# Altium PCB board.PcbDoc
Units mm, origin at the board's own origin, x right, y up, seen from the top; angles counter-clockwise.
Board outline 68 x 91 mm, 2 copper layers (Top Layer, Bottom Layer), stack 0.396 mm thick; 85 components, 65 nets, 273 pads, 165 vias.
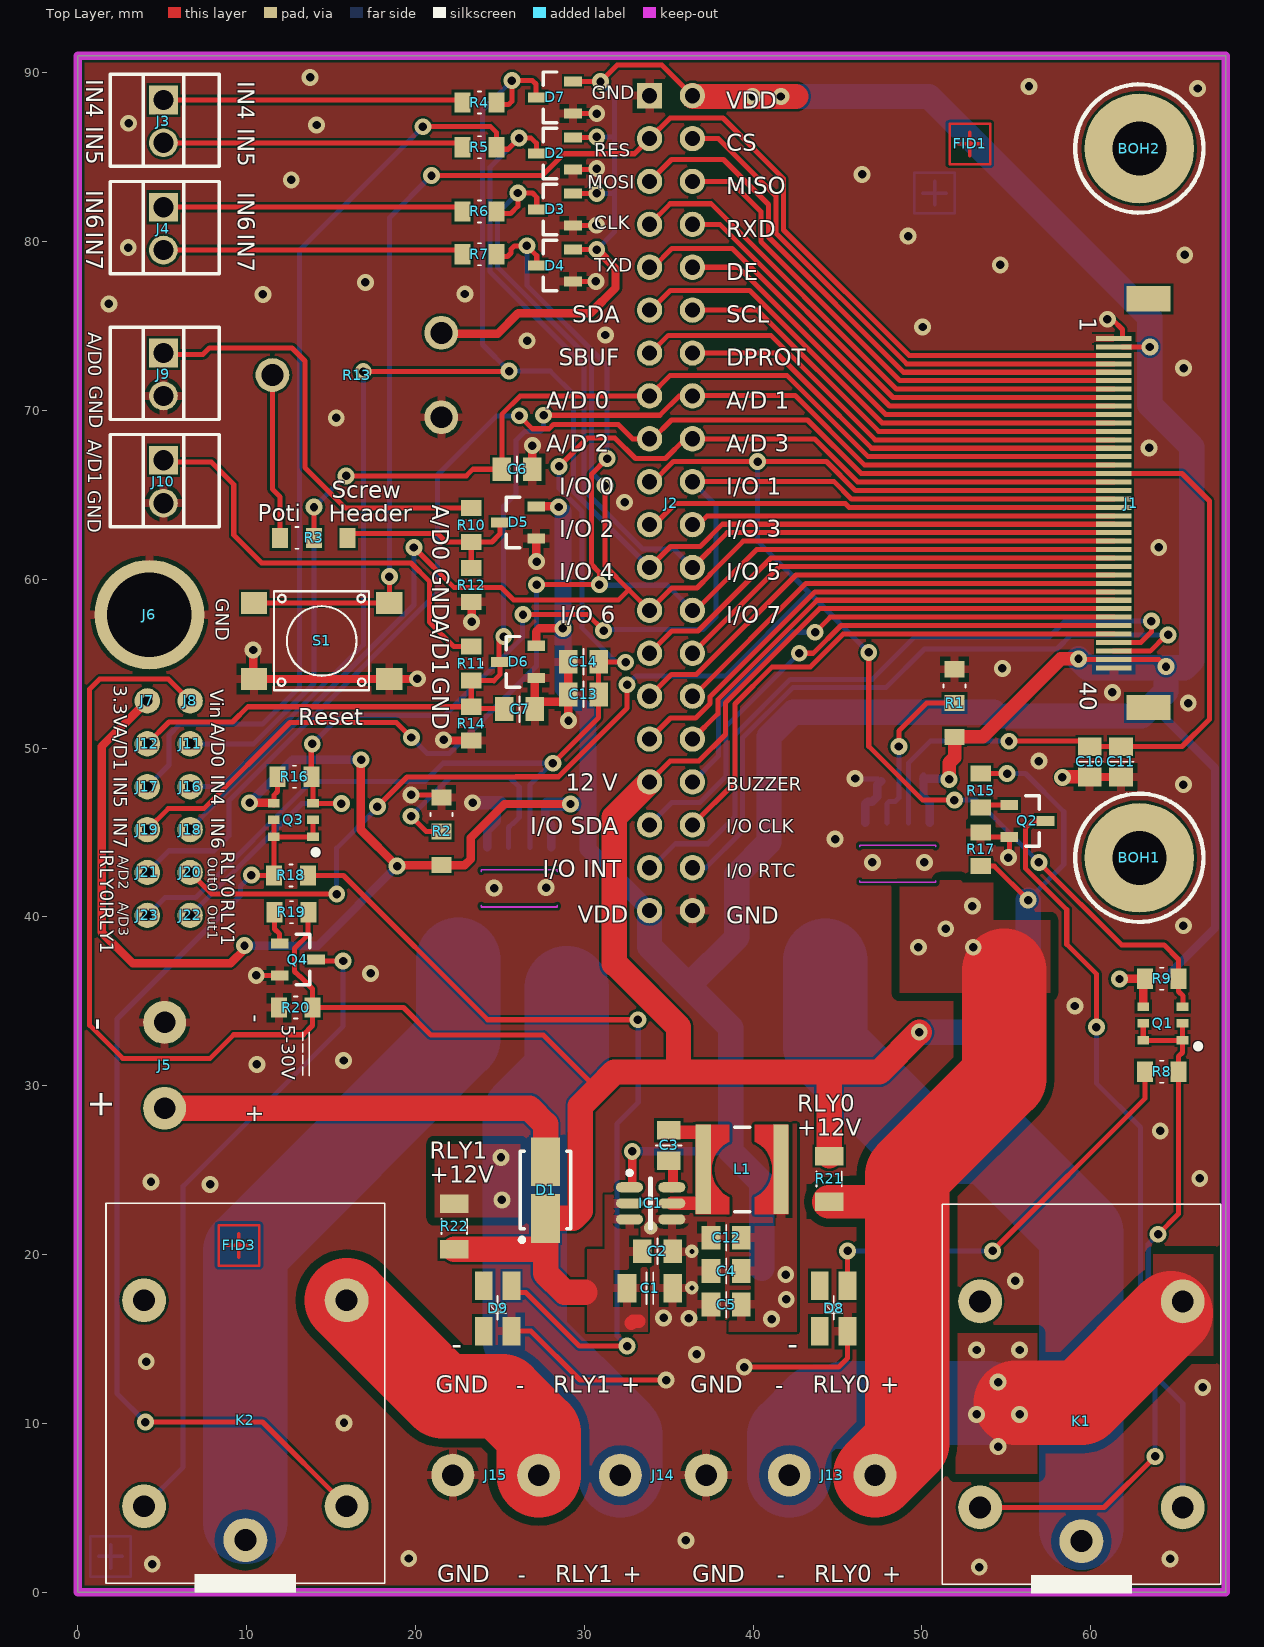
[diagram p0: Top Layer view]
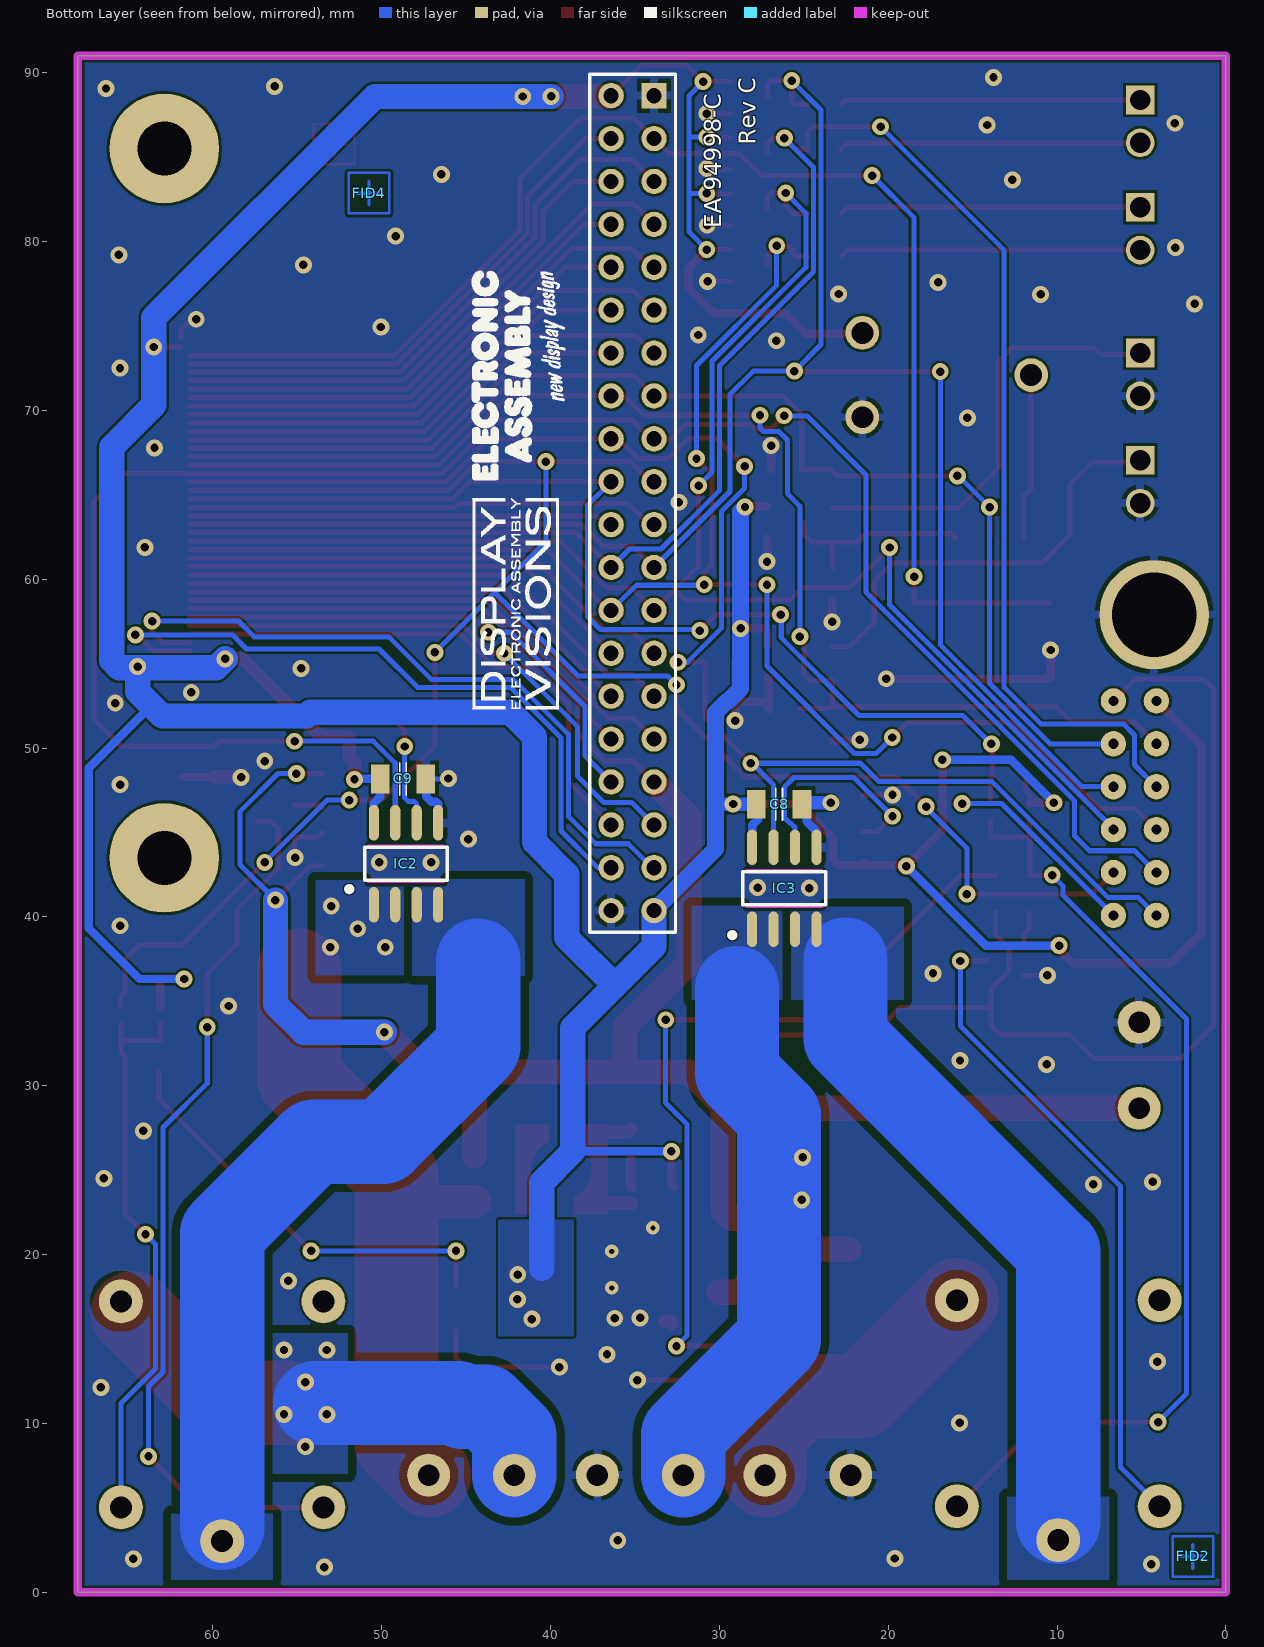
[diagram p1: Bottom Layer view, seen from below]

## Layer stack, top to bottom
Top Layer: signal copper 0.018
Dielectric: prepreg 0.36, FR-4, Dk 4.8
Bottom Layer: signal copper 0.018

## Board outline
0,0 68,0 68,91 0,91

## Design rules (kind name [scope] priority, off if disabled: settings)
Clearance Clearance_RelaisA [OnLayer('Keep-Out Layer') or InNet('K1IN') OR InNet('K1INAMP') OR InNet('K1OUT') OR InNet('K2IN') OR InNet('K2INAMP') OR InNet('K2OUT') vs InComponent('IC2') or InComponent('IC3')] p1: gap=0.2
Clearance Clearance_Relais [(InNet('K1IN') OR InNet('K1INAMP') OR InNet('K1OUT') OR InNet('K2IN') OR InNet('K2INAMP') OR InNet('K2OUT'))] p2: gap=0.5
Clearance Clearance-xPP-xTP-xTT [All] p3: gap=0.15
ComponentClearance [All] p1: gap=0.25 collisioncheckmode=3 verticalgap=0.25 showdistances=FALSE
DiffPairsRouting [All] p1: maxlimit=0.25 minlimit=0.25 mostfreqgap=0.25 maxuncoupledlength=12.5
Height [All] p1: minheight=0 maxheight=25 prefheight=12.5
HoleSize HoleSize-PTH [All] p1: absolutevalues=TRUE maxlimit=5 minlimit=0.25 maxpercent=80.000 minpercent=20.000
HoleToHoleClearance [All] p1: gap=0.15 allowstackedmicrovias=TRUE
MinimumAnnularRing MinimumAnnularRing_oval [InNetClass('Flash')] p1: minimumring=0
MinimumAnnularRing "Minimum IAR  >0.45mm" [((ObjectKind = 'Pad') OR (ObjectKind = 'Via')) And (Layer = 'MultiLayer') And (HoleDiameter > AsMM(0.45))] p2: minimumring=0.1 // minimum inner annular ring for pads > 0.45mm finished hole size
MinimumAnnularRing "Minimum IAR <=0.45mm" [((ObjectKind = 'Pad') OR (ObjectKind = 'Via')) And (Layer = 'MultiLayer') And (HoleDiameter <= AsMM(0.45))] p3: minimumring=0.25 // minimum inner annular ring for pads <= 0.45mm finished hole size
MinimumSolderMaskSliver [All] p1: minsoldermaskwidth=0.075
PlaneClearance PlaneClearance-IPI [All] p1: clearance=0.4
PlaneConnect [All] p1: planeconnectstyle=Relief reliefexpansion=0.4 reliefentries=4 reliefconductorwidth=0.4 reliefairgap=0.2
PolygonConnect PolygonConnectVia [All vs IsVia] p1: connectstyle=Direct reliefconductorwidth=0.254 reliefentries=4 polygonreliefangle="90 Angle" airgapwidth=0.254
PolygonConnect PolygonConnectRelais [InNet('K1IN') or InNet('K1INAMP') or InNet('K2IN') or InNet('K2INAMP') or InNet('K1OUT')] p2: connectstyle=Direct reliefconductorwidth=0.254 reliefentries=4 polygonreliefangle="90 Angle" airgapwidth=0.254
PolygonConnect PolygonConnect-xTW [All] p3: connectstyle=Relief reliefconductorwidth=0.5 reliefentries=4 polygonreliefangle="90 Angle" airgapwidth=0.254
RoutingCorners [All] p1: cornerstyle=45-Degree minsetback=2.5 maxsetback=2.5
RoutingVias "RoutingVias > 0.45mm" [(ObjectKind = 'Via') And (HoleDiameter > AsMM(0.45))] p1: holewidth=0.5 width=1 viastyle="Through Hole" minholewidth=0.45 minwidth=0.95 maxholewidth=0.9 maxwidth=1.4 // finishet hole size > 0.45mm
RoutingVias "RoutingVias <= 0.45mm" [(ObjectKind = 'Via') And (HoleDiameter <= AsMM(0.45))] p2: holewidth=0.3 width=0.8 viastyle="Through Hole" minholewidth=0.25 minwidth=0.7 maxholewidth=0.5 maxwidth=1 // finishet hole size <= 0.45mm
SilkToSilkClearance [All] p1: silktosilkclearance=0.05
SilkscreenOverComponentPads [All] p1: minsilkscreentomaskgap=0.1
SolderMaskExpansion SolderMaskExpansionVia [IsVia] p1: expansion=-2
SolderMaskExpansion [All] p2: expansion=0.1
Width Relais [(InNet('K1IN') OR InNet('K1INAMP') OR InNet('K1OUT') OR InNet('K2IN') OR InNet('K2INAMP') OR InNet('K2OUT'))] p1: maxlimit=10 minlimit=2 preferedwidth=5
Width Width-xTW [All] p2: maxlimit=1.5 minlimit=0.15 preferedwidth=0.3
17 further rules are at their usual default settings.

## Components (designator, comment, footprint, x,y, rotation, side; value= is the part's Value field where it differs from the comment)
BOH1 "Bohrung" BOH_3_2 62.868,43.5 r0 top locked
BOH2 "Bohrung" BOH_3_2 62.868,85.5 r0 top locked
C1 "C1206" C1206 33.884,18.009 r180 top
C2 "C0805" C0805 34.334,20.193 r180 top
C3 "C0805" C0805 35.001,26.467 r270 top
C4 "C0805" C0805 38.405,19.03 r0 top
C5 "C0805" C0805 38.404,17.044 r0 top
C6 "C0805" C0805 26.019,66.506 r180 top
C7 "C0805" C0805 26.171,52.308 r180 top
C8 "C1206" C1206 26.458,46.669 r180 bottom
C9 "C1206" C1206 48.734,48.167 r180 bottom
C10 "C0805" C0805 59.928,49.183 r90 top
C11 "C0805" C0805 61.782,49.183 r90 top
C12 "C0805" C0805 38.405,21.006 r0 top
C13 "C0805" C0805 29.956,53.171 r0 top
C14 "C0805" C0805 29.956,55.102 r0 top
D1 "B330A" SMA 27.711,23.825 r90 top
D2 "BAT54S" SOT23-3 28.262,85.209 r180 top
D3 "BAT54S" SOT23-3 28.262,81.89 r180 top
D4 "BAT54S" SOT23-3 28.262,78.571 r180 top
D5 "BAT54S" SOT23-3 26.078,63.357 r180 top
D6 "BAT54S" SOT23-3 26.078,55.102 r180 top
D7 "BAT54S" SOT23-3 28.262,88.528 r180 top
D8 "LED_RedGreen" LEDDUO1210 44.767,16.815 r90 top
D9 "LED_RedGreen" LEDDUO1210 24.867,16.815 r90 top
FID1 "Fiducial" Fiducial 52.832,85.776 r90 top
FID2 "Fiducial" Fiducial 1.956,2.134 r90 bottom
FID3 "Fiducial" Fiducial 9.55,20.549 r90 top
FID4 "Fiducial" Fiducial 50.749,82.855 r90 bottom
IC1 "AP63203" TSOT26 33.934,23.038 r0 top
IC2 "CurrentMonitor" SOIC8_CURRENT 48.556,43.147 r90 bottom
IC3 "CurrentMonitor" SOIC8_CURRENT 26.153,41.69 r90 bottom
J1 "ZIFF40-0.5" "ZIFF40-0.5 - LONG" 61.868,74.25 r270 top locked
J2 "PINHeader2x20" PINHDR2X20 33.868,88.63 r0 top locked
J3 "SCREWHeader1x2" SCREWHDR1X2 5.082,85.836 r270 top
J4 "SCREWHeader1x2" SCREWHDR1X2 5.082,79.486 r270 top
J5 "AKS-2" SCREWHDR1X2_Big 5.147,33.749 r270 top
J6 "TP" PAD50/65 4.251,57.894 r270 top
J7 "TP" PAD06/15 4.124,52.789 r270 top
J8 "TP" PAD06/15 6.664,52.789 r270 top
J9 "AKM-2" SCREWHDR1X2 5.082,70.85 r270 top
J10 "SCREWHeader1x2" SCREWHDR1X2 5.082,64.5 r270 top
J11 "TP" PAD06/15 6.664,50.249 r270 top
J12 "TP" PAD06/15 4.124,50.249 r0 top
J13 "AKS-2" SCREWHDR1X2_Big 47.218,6.944 r180 top
J14 "AKS-2" SCREWHDR1X2_Big 37.218,6.944 r180 top
J15 "AKS-2" SCREWHDR1X2_Big 27.298,6.944 r180 top
J16 "TP" PAD06/15 6.664,47.709 r0 top
J17 "TP" PAD06/15 4.124,47.709 r0 top
J18 "TP" PAD06/15 6.664,45.169 r0 top
J19 "TP" PAD06/15 4.124,45.169 r270 top
J20 "TP" PAD06/15 6.664,42.629 r0 top
J21 "TP" PAD06/15 4.124,42.629 r270 top
J22 "TP" PAD06/15 6.664,40.089 r0 top
J23 "TP" PAD06/15 4.124,40.089 r0 top
K1 "G5LE" G5LE 59.442,3.029 r90 top
K2 "G5LE" G5LE 9.931,3.099 r90 top
L1 "Inductor-1919" L_1919 39.345,25.044 r90 top
Q1 "MFPS6702" TSOP-6 65.428,32.688 r180 top
Q2 "TRS847-C" SOT23-3 56.245,45.678 r0 top
Q3 "MFPS6702" TSOP-6 13.942,44.738 r180 top
Q4 "TRS847-C" SOT23-3 13.039,37.474 r0 top
R1 "R0805_double" R0805_double 51.927,53.663 r270 top
R2 "R0805_double" R0805_double 21.548,46.069 r270 top
R3 "R0805_double" R0805_double 12.988,62.442 r0 top
R4 "R0805" R0805 23.792,88.223 r0 top
R5 "R0805" R0805 23.792,85.582 r0 top
R6 "R0805" R0805 23.792,81.772 r0 top
R7 "R0805" R0805 23.792,79.232 r0 top
R8 "R0805" R0805 64.195,30.836 r0 top
R9 "R0805" R0805 64.195,36.331 r0 top
R10 "R0805" R0805 23.309,63.204 r90 top
R11 "R0805" R0805 23.309,55 r90 top
R12 "R0805" R0805 23.309,59.648 r90 top
R13 "V10" V10 16.535,72.085 r180 top
R14 "R0805" R0805 23.309,51.444 r90 top
R15 "R0805" R0805 53.476,47.482 r90 top
R16 "R0805" R0805 12.836,48.294 r180 top
R17 "R0805" R0805 53.476,44.002 r90 top
R18 "R0805" R0805 12.633,42.452 r180 top
R19 "R0805" R0805 12.66,40.268 r0 top
R20 "R0805" R0805 12.914,34.629 r180 top
R21 "R1206" R1206 44.501,24.486 r270 top
R22 "R1206" R1206 22.301,21.666 r90 top
S1 "SMD Taster" TASTER_SMD 14.453,56.337 r0 top

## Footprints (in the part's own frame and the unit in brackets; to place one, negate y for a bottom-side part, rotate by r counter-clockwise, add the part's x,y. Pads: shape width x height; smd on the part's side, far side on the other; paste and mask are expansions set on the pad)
BOH_3_2 [mm] "Bohrung 6.5 / 3.2 mm"
  round 6.5 hole 3.2: 1(0,0)
  silkscreen extent -3.8,-3.8 3.8,3.8
C0805 [mm] "Chip Capacitor, 2-Leads, Body 2,0x1,3mm, IPC Medium Density"
  rect 1.1x1.4 smd: 1(-0.9,0) 2(0.9,0)
  silkscreen extent 0,-0.76 0,0.76, body extent -1,-0.62 1,0.63, height 0.78
C1206 [mm] "Chip Capacitor, 2-Leads, Body 2 IPC Medium Density"
  rect 1.1x1.7 smd: 1(-1.35,0) 2(1.35,0)
  silkscreen extent -0.2,-0.95 0.2,0.95, body extent -1.6,-0.8 1.6,0.8, height 1
Fiducial [mm]
  Top Layer lines w0.15: -1.2,1.2 -1.2,-1.2 1.2,-1.2 1.2,1.2 -1.2,1.2
  Top Layer lines w0.2: 0,0.7 0,-0.7 ; -0.7,0 0.7,0
G5LE [mm] "Relais"
  round 2.6 hole 1.3: 1(0,0) 2(2,-6) 3(14.2,-6) 4(14.2,6) 5(2,6)
  silkscreen extent -3.1,-8.25 19.95,8.25, body extent -2.55,-8.25 19.95,8.25, height 19
L_1919 [mm] "WE-TPC_4828 Power Inductor, SMD, 2-Leads, body 4.8x4.8mm"
  rect 5.3x0.9 smd paste-403.566 mask-403.566: 1(0,2.3) 2(0,-2.3)
  Top Layer region: -2.65,0.75 -1.636,0.75 -1.636,0.75 -1.138,1.394 -0.407,1.753 0.407,1.753 1.138,1.394 1.636,0.75 1.636,0.75 2.65,0.75 2.65,0.75 2.65,2.75 -2.65,2.75
  Top Layer region: 2.65,-0.75 1.636,-0.75 1.636,-0.75 1.138,-1.394 0.407,-1.753 -0.407,-1.753 -1.138,-1.394 -1.636,-0.75 -1.636,-0.75 -2.65,-0.75 -2.65,-0.75 -2.65,-2.75 2.65,-2.75
  silkscreen extent -2.5,-0.45 2.5,0.45, body extent -2.4,-2.4 2.4,2.4, height 2.8
LEDDUO1210 [mm] "Duo Led 1210"
  rect 1.7x1.05 smd: 1(-1.35,0.825) 2(1.35,0.825) 3(-1.35,-0.825) 4(1.35,-0.825)
  silkscreen extent -0.66,-0.51 0.74,0.51, body extent -1.5,-1.25 1.5,1.25, height 1.35
PAD06/15 [mm]
  round 1.5 hole 0.6: 1(0,0)
PAD50/65 [mm] "Oszi_Klammer passt"
  round 6.5 hole 5: 1(0,0)
PINHDR2X20 [mm] "Stiftleiste"
  rect 1.5x1.5 hole 0.9: 1(0,0)
  round 1.5 hole 0.9: 2(2.54,0) 3(0,-2.54) 4(2.54,-2.54) 5(0,-5.08) 6(2.54,-5.08) 7(0,-7.62) 8(2.54,-7.62) 9(0,-10.16) 10(2.54,-10.16) 11(0,-12.7) 12(2.54,-12.7) 13(0,-15.24) 14(2.54,-15.24) 15(0,-17.78) 16(2.54,-17.78) 17(0,-20.32) 18(2.54,-20.32) 19(0,-22.86) 20(2.54,-22.86) 21(0,-25.4) 22(2.54,-25.4) 23(0,-27.94) 24(2.54,-27.94) 25(0,-30.48) 26(2.54,-30.48) 27(0,-33.02) 28(2.54,-33.02) 29(0,-35.56) 30(2.54,-35.56) 31(0,-38.1) 32(2.54,-38.1) 33(0,-40.64) 34(2.54,-40.64) 35(0,-43.18) 36(2.54,-43.18) 37(0,-45.72) 38(2.54,-45.72) 39(0,-48.26) 40(2.54,-48.26)
  body extent -1.27,-49.53 3.81,1.27, height 8.52
R0805 [mm] "Chip Resistor, 2-Leads, Body 2,0x1,3mm, IPC Medium Density"
  rect 0.95x1.2 smd: 1(-1,0) 2(1,0)
  silkscreen extent -0.1,-0.65 0.1,0.65, body extent -1,-0.62 1,0.63, height 0.78
R0805_double [mm] "Chip Resistor, 3-Leads, Body 4,0x1,3mm, IPC Medium Density"
  rect 0.95x1.2 smd: 1(-1,0) 2(1,0)
  rect 0.95x1.2 smd paste-10: 3(3,0)
  silkscreen extent -0.1,-0.65 0.1,0.65, body extent -1,-0.62 1,0.63, height 0.78
R1206 [mm] "Chip Resistor, 2-Leads, Body 3,1x1,6mm, IPC Medium Density"
  rect 1.1x1.7 smd: 1(-1.35,0) 2(1.35,0)
  silkscreen extent -0.45,-0.75 0.45,0.75, body extent -1.6,-0.8 1.6,0.8, height 1
SCREWHDR1X2 [mm] "Klemmleiste"
  rect 1.7x1.7 hole 1.2: 1(-2.54,0)
  round 1.7 hole 1.2: 2(0,0)
  silkscreen extent -4.06,-3.15 1.4,3.3, body extent -4.01,-3.25 1.47,3.25, height 8.55
SCREWHDR1X2_Big [mm] "AKM-2"
  round 2.54 hole 1.27: 1(0,0) 2(5.08,0)
  Mechanical 13 keep-out lines w0.102: -2.54,-3.81 7.468,-3.81 7.468,4.191
  body extent -3.1,-4 8.1,5, height 12.5
SMA [mm] "Molded Diode, 2-Leads, Body 4.3x2.6mm, IPC Low Density"
  rect 2.9x1.7 smd: 1(1.675,0) 2(-1.675,0)
  silkscreen extent -3.07,-1.5 2.3,1.52, body extent -2.3,-1.46 2.3,1.46, height 2.4
SOIC8_CURRENT [mm] "SOIC, 8-Leads, Body 4,9x3,9mm (max), Pitch 1,27mm, KeepOut"
  oval 2.1x0.6 smd: 1(-2.425,1.905) 2(-2.425,0.635) 3(-2.425,-0.635) 4(-2.425,-1.905) 5(2.425,-1.905) 6(2.425,-0.635) 7(2.425,0.635) 8(2.425,1.905)
  Keep-Out Layer lines w0.1: -1,-2.25 -1.1,-2.25 -1.1,2.25 -1,2.25 ; 1,-2.25 1.1,-2.25 1.1,2.25 1,2.25
  silkscreen extent -0.97,-2.45 0.98,2.45, body extent -3.1,-2.5 3.1,2.5, height 1.75
SOT23-3 [mm] "SOT23, 3-Leads, Body 3,0x2,5mm (max), Pitch 0,95mm, IPC Medium Density"
  rect 1.05x0.6 smd: 1(-1.075,0.95) 2(-1.075,-0.95) 3(1.075,0)
  silkscreen extent -0.1,-1.5 0.7,1.5, body extent -0.7,-1.5 0.7,1.5, height 1.1
TASTER_SMD [mm] "TASTS-1P7MM"
  rect 1.55x1.3 smd: 1(-4,2.25) 1(4,2.25) 2(-4,-2.25) 2(4,-2.25)
  silkscreen extent -2.82,-2.92 2.79,2.95, body extent -3.1,-3.1 3.1,3.1, height 6.9
TSOP-6 [mm]
  rect 0.7x0.5 smd: 1(0,0) 1(0,-1.001) 1(2.325,-1.001) 1(2.325,0) 3(0,-2.002) 4(2.325,-2.002)
  body extent 0.27,-2.4 2.05,0.5, height 1.3
TSOT26 [mm] "6 pin 0.95 pitch"
  oval 1.6x0.6 smd: 1(-1.25,0.95) 2(-1.25,0) 3(-1.25,-0.95) 4(1.25,-0.95) 5(1.25,0) 6(1.25,0.95)
  silkscreen extent -1.37,-1.5 0.05,1.92, body extent -0.85,-1.5 0.85,1.5, height 1
V10 [mm] "Potentiometer V10"
  round 2 hole 1.3: 1(-5,2.5) 2(-5,-2.5) 3(5,0)
  body extent -5.38,-5.15 5.57,5.15, height 6.6
"ZIFF40-0.5 - LONG" [mm] "Ziff Stecker 0.5 pitch 40 pins"
  rect 1.5x2.6 smd: 0(-2.35,1.55) 0(21.85,1.55)
  rect 0.3x2.1 smd: 1(0,-0.5) 2(0.5,-0.5) 3(1,-0.5) 4(1.5,-0.5) 5(2,-0.5) 6(2.5,-0.5) 7(3,-0.5) 8(3.5,-0.5) 9(4,-0.5) 10(4.5,-0.5) 11(5,-0.5) 12(5.5,-0.5) 13(6,-0.5) 14(6.5,-0.5) 15(7,-0.5) 16(7.5,-0.5) 17(8,-0.5) 18(8.5,-0.5) 19(9,-0.5) 20(9.5,-0.5) 21(10,-0.5) 22(10.5,-0.5) 23(11,-0.5) 24(11.5,-0.5) 25(12,-0.5) 26(12.5,-0.5) 27(13,-0.5) 28(13.5,-0.5) 29(14,-0.5) 30(14.5,-0.5) 31(15,-0.5) 32(15.5,-0.5) 33(16,-0.5) 34(16.5,-0.5) 35(17,-0.5) 36(17.5,-0.5) 37(18,-0.5) 38(18.5,-0.5) 39(19,-0.5) 40(19.5,-0.5)
  body extent -3.48,-0.01 22.92,5.09, height 2.15

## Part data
C1 C2 C3 C4 C5 C6 C7 C8 C9 C10 C11 C12 C13 C14: library part Capacitor, "Capacitor"
D1: "Schottky"
D8 D9: "LED red green 1210"
IC1: library part AP63200
IC2 IC3: library part ACS70331, "High Sensitivity, 1 MHz, GMR-Based Current Sensor IC"
J2: "Pin strip 2x20"
J3 J4 J10: "Screw terminal 1x2"
J5 J13 J14 J15: library part SCREWHeader1x2_Big, "Screw terminal 1x2"
J9: library part SCREWHeader1x2, "Screw terminal 1x2"
K1 K2: "Relais"
R1 R2 R3: library part Resistor_double, "Resistor"
R4 R5 R6 R7 R8 R9 R10 R11 R12 R14 R15 R16 R17 R18 R19 R20 R21 R22: library part Resistor, "Resistor"
R13: library part Potentiometer, "Potentiometer"
S1: library part SW-1P7, "Switch, Knackfrosch"

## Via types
v1: diameter 1, hole 0.5, Top Layer to Bottom Layer, 162 vias
v2: diameter 0.8, hole 0.3, Top Layer to Bottom Layer, 3 vias

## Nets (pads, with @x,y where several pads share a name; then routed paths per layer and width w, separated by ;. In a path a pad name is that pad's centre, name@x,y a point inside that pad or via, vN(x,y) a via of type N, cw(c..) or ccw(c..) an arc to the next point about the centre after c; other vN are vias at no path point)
12V: C1.2 C2.2 D1.2 IC1.2 IC1.3 J1.33 J2.33 J8.1 R15.2 R17.1 R19.2 R20.1 R21.1 R22.1 | length 196.5
  Top Layer w0.3: J8.1 5.376,54.077 1.295,54.077 0.711,53.492 0.711,33.579 2.667,31.623 7.849,31.623 9.246,33.02 13.36,33.02 13.914,33.574 R20.1 ; R19.2 13.649,40.257 13.649,38.947 12.839,38.138 12.839,36.771 13.103,36.507 13.143,36.507 13.914,35.735 R20.1 ; 30.772,29.807 27.584,32.995 20.93,32.995 19.295,34.629 R20.1 ; J2.33 33.868,48.016 35.086,49.234 36.788,49.234 38.358,50.804 38.358,52.672 43.936,58.25 J1.33 ; R17.1 54.28,43.002 v1(56.286,40.996) ; R15.2 53.483,48.489 v1(55.042,48.489)
  Top Layer w0.8: 32.791,15.951 32.893,16.053 33.223,16.053
  Top Layer w1.5: R22.1 27.711,20.316 ; 30.048,17.78 28.829,17.78 27.711,18.898 27.711,20.316 ; J2.33 31.772,45.894 31.772,37.211 31.85,37.211 35.585,33.476 35.585,30.81 ; R21.1 44.501,30.759 ; v1(49.835,33.172) 47.473,30.81 35.585,30.81 ; 27.711,20.316 D1.2 29.338,22.15 29.769,22.581 29.769,28.804 30.772,29.807 31.775,30.81 35.585,30.81
  Bottom Layer w0.3: v1(55.042,48.489) 56.134,48.489 58.395,46.228 58.395,43.104 v1(56.286,40.996)
  Bottom Layer w1.5: v1(49.835,33.172) 54.635,33.172 56.286,34.823 v1(56.286,40.996)
A/D_0: C6.2 J1.15 J2.15 J11.1 R3.2 | length 75.6
  Top Layer w0.3: R3.2 13.988,64.255 v1(13.995,64.262) ; v1(15.9,66.116) 23.012,66.116 23.402,66.506 C6.2 25.119,69.76 26.208,70.85 J2.15 35.088,72.069 41.999,72.069 46.818,67.25 J1.15
  Bottom Layer w0.3: J11.1 10.422,50.249 13.995,53.823 v1(13.995,64.262) 15.85,66.116 v1(15.9,66.116)
A/D_1: C7.2 D6.3 J1.16 J2.16 J12.1 R11.1 R14.2 | length 78.7
  Top Layer w0.3: J12.1 5.411,51.537 9.169,51.537 10.077,52.444 R14.2 ; v1(25.231,56.6) 24.952,56.6 24.952,55.153 D6.3 25.003,54.34 24.647,53.984 24.631,54 R11.1 R14.2 ; C7.2@25.271,52.344 23.409,52.344 R14.2 ; v1(27.593,69.707) 34.477,69.707 35.62,70.85 J2.16 36.441,70.882 42.478,70.882 46.611,66.75 J1.16
  Bottom Layer w0.3: v1(25.231,56.6) 25.231,64.322 25.968,65.058 25.968,68.233 26.476,68.741 27.39,68.741 27.593,68.945 v1(27.593,69.707)
A/D_2: C10.2 C11.2 IC2.7 J1.17 J2.17 J21.1 | length 118.2
  Top Layer w0.3: v1(26.162,69.672) 26.928,68.907 27.925,68.907 28.17,69.151 32.017,69.151 32.859,68.31 J2.17 34.054,68.31 35.171,69.427 43.226,69.427 46.404,66.25 J1.17 65.391,66.25 67.02,64.621 67.02,51.703 65.4,50.083 C11.2 C10.2 59.608,50.403 v1(55.152,50.403)
  Bottom Layer w0.3: J21.1 5.411,43.917 8.077,43.917 8.966,44.806 8.966,46.884 21.311,59.229 21.311,66.167 24.816,69.672 v1(26.162,69.672) ; IC2.7 49.191,49.099 50.494,50.403 v1(55.152,50.403)
A/D_3: C13.2 C14.2 IC3.7 J1.18 J2.18 J23.1 | length 91.1
  Top Layer w0.3: v1(28.143,49.098) 30.856,51.811 C13.2 C14.2 32.419,55.102 v1(32.445,55.076) ; v1(28.508,66.675) 30.193,68.36 31.81,68.36 33.029,67.141 34.814,67.141 35.983,68.31 J2.18 43.629,68.31 46.189,65.75 J1.18
  Bottom Layer w0.3: J23.1 5.174,41.139 6.976,41.139 13.865,48.028 20.57,48.028 21.641,49.098 v1@28.067,49.098 ; IC3.7 26.788,47.819 v1@28.067,49.098 ; v1(28.143,49.098) v1@28.067,49.098 ; v1(28.508,66.675) 28.508,65.377 29.879,64.005 29.879,57.094 31.898,55.076 v1(32.445,55.076)
BUZZER: J1.34 J2.34 | length 30.7
  Top Layer w0.3: v1(43.672,56.854) 44.567,57.75 J1.34
  Bottom Layer w0.3: J2.34 37.957,49.538 37.957,52.46 42.351,56.854 v1(43.672,56.854)
CLK: J1.7 J2.7 | length 32.6
  Top Layer w0.3: J2.7 35.088,82.229 37.516,82.229 48.495,71.25 J1.7
CS: J1.4 J2.4 | length 31.8
  Top Layer w0.3: J2.4 37.94,86.09 41.354,82.675 41.354,80.489 49.094,72.75 J1.4
DE: J1.10 J2.10 | length 28.6
  Top Layer w0.3: J2.10 39.134,78.47 47.854,69.75 J1.10
DPROT: J1.14 J2.14 | length 27.3
  Top Layer w0.3: J2.14 41.385,73.39 43.282,71.493 47.025,67.75 J1.14
GND: C1.1 C2.1 C4.1 C5.1 C6.1 C7.1 C8.2 C9.2 C10.1 C11.1 C12.1 C13.1 C14.1 D2.1 D3.1 D4.1 D5.1 D6.1 D7.1 D8.3 D9.3 IC1.4 IC2.5 IC3.5 J1.1 J1.40 J2.1 J2.40 J5.1 J6.1 J9.2 J10.2 J14.1 J15.2 Q2.2 Q4.2 R1.1 R2.1 R12.1 R13.1 R14.1 R17.2 R20.2 S1.2 | length 69.3
  Top Layer w0.3: v1(10.575,36.534) 10.586,36.524 Q4.2@11.71,36.524 ; Q4.2@11.66,36.474 Q4.2@11.71,36.524 ; Q4.2@11.914,36.474 Q4.2 Q4.2@11.71,36.524 ; v1(19.745,47.228) 21.389,47.228 R2.1 ; D9.3 26.852,15.465 29.743,12.573 v1(34.849,12.573) ; D4.1 30.682,77.621 v1(30.692,77.631) ; D3.1 30.699,80.94 v1(30.718,80.959) ; D2.1 30.69,84.259 v1(30.743,84.312) ; D7.1 30.728,87.578 v1(30.743,87.563) ; v1(39.472,13.335) 45.06,13.335 45.592,13.867 D8.3 ; R17.2 53.75,44.728 Q2.2 55.17,43.527 55.178,43.519 55.169,43.51 v1(55.118,43.51) ; v1(60.978,75.39) 61.263,75.39 61.868,74.785 J1.1@61.868,74.25
  Top Layer w0.5: v1(10.389,55.804) 10.389,54.151 10.453,54.087 18.453,54.087 20.102,54.087 v1(20.117,54.102) ; v1(21.675,50.479) 21.71,50.444 R14.1 ; R12.1 23.326,58.631 v1(23.326,57.464) ; C6.1 26.919,67.889 v1(26.933,67.903) ; C7.1 C7.1@27.071,52.573 ; D6.1 27.071,54.07 C7.1@27.071,52.573 ; D5.1 27.153,61.061 v1(27.178,61.036) ; C14.1 C13.1 ; v1(29.067,51.622) 29.056,51.633 C13.1 ; C10.1 C11.1 ; C7.1@27.071,52.573 27.238,52.739 28.624,52.739 C13.1
  Top Layer w0.8: v1(58.318,48.26) 58.342,48.283 C10.1
  Bottom Layer w0.3: v1(46.041,48.193) 46.067,48.167 C9.2 ; v1(60.978,75.39) v1@60.978,75.523
  Bottom Layer w0.5: IC3.5 24.248,45.069 24.832,45.653 24.832,46.393 C8.2 ; IC2.5 46.651,46.694 46.778,46.821 47.057,46.821 47.362,47.126 47.362,47.816 C9.2@47.587,48.04
  Bottom Layer w0.8: v1(23.393,46.761) 25.015,46.761 C8.2
  other v1: 53.391,1.499 4.42,1.676 64.694,1.981 19.609,2.007 36.017,3.073 15.773,10.033 66.624,12.141 4.064,13.665 36.652,14.097 36.195,16.231 34.696,16.256 55.524,18.44 7.849,24.155 4.343,24.308 66.446,24.511 64.11,27.33 10.617,31.267 15.748,31.496 59.055,34.722 17.348,36.652 65.481,39.472 24.663,41.707 27.737,41.732 47.066,43.231 50.14,43.231 44.856,44.602 65.481,47.828 56.921,49.225 65.77,52.663 61.274,53.298 54.762,54.712 64.017,61.883 32.394,64.55 63.449,67.767 15.316,69.545 65.49,72.501 26.619,74.117 31.251,74.456 50.038,74.93 1.854,76.302 10.973,76.86 22.936,76.886 17.043,77.572 54.635,78.613 65.557,79.197 2.997,79.629 49.174,80.315 12.649,83.642 46.457,83.972 14.148,86.893 3.023,86.995 66.319,89.052 56.337,89.179 13.767,89.713
  other v2: 36.373,18.034 36.373,20.193 33.934,21.578
I/O_0_0: J1.19 J2.19 J20.1 Q1.3 R9.2 | length 121.8
  Top Layer w0.3: J20.1 7.942,41.351 v1(15.342,41.351) ; v1(17.755,46.533) 19.507,48.285 25.933,48.285 25.946,48.298 28.475,48.298 32.537,52.361 v1(32.537,53.746) ; J2.19 34.079,65.77 35.273,66.963 v1(40.268,66.963) 44.339,66.963 46.053,65.25 J1.19 ; v1(46.847,55.66) 46.847,50.105 50.038,46.914 v1(51.918,46.914) ; v1(56.921,43.231) 61.824,38.329 64.338,38.329 65.195,37.472 R9.2 65.195,35.585 65.465,35.315 65.465,34.728 Q1.3
  Bottom Layer w0.3: v1(15.342,41.351) 15.342,44.069 17.755,46.482 v1(17.755,46.533) ; v1(32.537,53.746) 33.067,54.276 38.376,54.276 43.303,59.204 ; v1(40.268,66.963) 40.268,62.239 43.303,59.204 ; v1(46.847,55.66) 43.303,59.204 ; v1(51.918,46.914) 53.238,46.914 v1(56.921,43.231)
I/O_0_1: J1.20 J2.20 J22.1 Q3.3 R16.1 | length 79.7
  Top Layer w0.3: v1(13.894,50.241) 13.836,50.183 R16.1 13.942,48.188 Q3.3 13.972,46.711 v1(15.621,46.711) ; v1(26.374,57.896) 30.21,57.896 v1(31.149,56.956) ; J2.20 44.798,65.77 45.818,64.75 J1.20
  Bottom Layer w0.3: J22.1 13.285,46.711 v1(15.621,46.711) ; v1(13.894,50.241) 15.581,51.929 21.728,51.929 26.336,56.537 26.336,57.857 v1(26.374,57.896) ; v1(31.149,56.956) 31.2,57.007 37.042,57.007 37.804,57.769 37.804,64.374 J2.20 J2.20@36.585,65.77
I/O_0_2: J1.21 J2.21 | length 28.1
  Top Layer w0.3: J2.21 34.155,63.23 35.4,64.474 45.457,64.474 45.681,64.25 J1.21
I/O_0_3: J1.22 J2.22 | length 25.2
  Top Layer w0.3: J2.22 36.763,63.23 37.283,63.75 J1.22
I/O_0_4: D7.3 J1.23 J2.23 J16.1 R4.2 | length 106.7
  Top Layer w0.3: v1(16.916,72.288) 25.527,72.288 v1(25.552,72.314) ; R4.2@24.792,88.096 25.511,88.096 25.714,88.299 v1(25.714,89.519) 26.933,89.519 27.136,89.315 27.136,88.579 D7.3 ; J2.23 35.113,61.934 36.864,61.934 38.18,63.25 J1.23
  Bottom Layer w0.3: J16.1 8.518,47.709 16.916,56.107 v1(16.916,72.288) ; v1(25.714,89.519) 23.976,87.78 23.976,73.891 v1(25.552,72.314) 27.991,72.314 29.362,70.942 29.362,65.196 J2.23
I/O_0_5: D2.3 J1.24 J2.24 J17.1 R5.2 | length 115.6
  Top Layer w0.3: v1(20.447,86.792) 24.46,86.792 24.792,86.46 R5.2 24.792,85.455 25.485,85.455 v1(26.146,86.115) 26.857,86.115 27.162,85.81 27.162,85.235 D2.3 ; J2.24 38.468,62.75 J1.24
  Bottom Layer w0.3: J17.1 5.41,48.995 5.41,50.775 6.045,51.41 10.946,51.41 13.132,53.595 13.132,79.477 v1(20.447,86.792) ; v1(26.146,86.115) 24.426,84.395 24.426,78.208 29.981,72.653 29.981,65.262 33.461,61.782 35.316,61.782 J2.24
I/O_0_6: D3.3 J1.25 J2.25 J18.1 R6.2 | length 98.8
  Top Layer w0.3: v1(19.914,61.874) 22.276,59.512 25.07,59.512 25.806,58.776 32.036,58.776 32.639,59.379 ; R6.2@24.792,81.645 25.638,81.645 26.069,82.076 v1(26.069,82.864) 26.933,82.864 27.187,82.609 D3.3 ; v1(31.226,65.541) 31.226,60.792 32.639,59.379 ; J1.25 39.415,62.25 37.458,60.293 37.458,60.255 36.674,59.47 35.189,59.47 J2.25 32.639,59.379
  Bottom Layer w0.3: J18.1 6.664,45.218 19.914,58.468 v1(19.914,61.874) ; v1(26.069,82.864) 24.876,81.67 24.876,78.47 30.431,72.914 30.431,66.336 v1(31.226,65.541)
I/O_0_7: D4.3 J1.26 J2.26 J19.1 R7.2 | length 95.9
  Top Layer w0.3: J19.1 5.361,46.406 7.468,46.406 12.573,51.511 18.872,51.511 v1(19.761,50.622) ; R7.2@24.792,79.105 25.46,79.105 25.663,79.308 25.663,79.536 25.866,79.74 v1(26.603,79.74) 27.187,79.155 D4.3 ; v1(27.178,59.665) 27.187,59.674 v1(30.895,59.674) 30.895,60.392 30.426,60.862 30.426,66.214 v1(31.353,67.141) ; J2.26 36.61,58.15 40.21,61.75 J1.26
  Bottom Layer w0.3: v1(19.761,50.622) 20.705,49.679 22.007,49.679 27.178,54.85 v1(27.178,59.665) ; v1(26.603,79.74) 26.603,77.403 31.353,72.653 v1(31.353,67.141) ; v1(30.895,59.674) 30.929,59.64 34.917,59.64 J2.26
I/O_CLK: J1.36 J2.36 | length 32.4
  Top Layer w0.3: J2.36 38.922,47.963 38.922,52.599 41.132,54.81 43.395,54.81 45.335,56.75 J1.36
I/O_INT: J1.37 J2.37 | length 41.7
  Top Layer w0.3: J1.37 62.955,56.25 63.585,56.88 v1(63.585,57.515)
  Bottom Layer w0.3: J2.37 33.969,42.91 35.391,44.332 37.322,44.332 38.926,45.936 38.926,50.787 42.202,54.064 47.054,54.064 49.572,56.582 57.547,56.582 58.48,57.515 v1(63.585,57.515)
I/O_RTC: J1.38 J2.38 | length 40.7
  Top Layer w0.3: J1.38@61.355,55.737 63.509,55.737 64.474,56.702 v1(64.576,56.702)
  Bottom Layer w0.3: J2.38 37.195,42.91 39.375,45.09 39.375,50.601 42.369,53.594 47.879,53.594 50.149,55.864 57.997,55.864 58.835,56.702 v1(64.576,56.702)
I/O_SDA: J1.35 J2.35 | length 34.1
  Top Layer w0.3: v1(42.732,55.61) 43.558,55.61 45.198,57.25 J1.35
  Bottom Layer w0.3: J2.35 35.189,46.77 36.839,46.77 38.407,48.338 38.407,51.284 v1(42.732,55.61)
IN0: J9.1 R10.2 | length 26.1
  Top Layer w0.3: J9.1 5.167,73.304 7.417,73.304 7.798,73.685 12.7,73.685 13.462,72.923 13.462,66.599 15.857,64.204 R10.2
IN0_4: J3.1 R4.1 | length 17.8
  Top Layer w0.3: J3.1 22.513,88.376 R4.1@22.792,88.096
IN0_5: J3.2 R5.1 | length 17.9
  Top Layer w0.3: J3.2 22.411,85.836 R5.1@22.792,85.455
IN0_6: J4.1 R6.1 | length 17.9
  Top Layer w0.3: J4.1 22.411,82.026 R6.1@22.792,81.645
IN0_7: J4.2 R7.1 | length 17.9
  Top Layer w0.3: J4.2 22.411,79.486 R7.1@22.792,79.105
IN1: J10.1 R11.2 | length 26
  Top Layer w0.3: J10.1 5.192,66.929 7.925,66.929 9.246,65.608 9.246,62.611 10.897,60.96 19.736,60.96 20.828,59.868 20.828,57.455 22.283,56 R11.2
K1IN: IC2.1 IC2.2 J13.1 R21.2 | length 37.7
  Top Layer w2: R21.2 48.994,23.136 49.117,23.012 49.117,23.067
  Top Layer w5: J13.1 49.117,8.844 49.117,23.012 ; 49.117,23.067 49.117,24.708 54.864,30.455 54.864,36.805
  other v1: 49.784,38.202 53.035,38.202 51.41,39.294 52.984,40.64
K1INAMP: IC2.3 IC2.4 K1.1 | length 42.3
  Bottom Layer w5: 44.272,37.414 44.272,32.334 49.911,26.695 54.026,26.695 59.442,21.28 K1.1@59.442,3.81
K1OUT: J13.2 K1.3 | length 26.3
  Top Layer w5: 55.55,11.227 59.439,11.227 K1.3@64.746,16.534
  Bottom Layer w5: J13.2 42.138,9.27 43.866,10.998 45.233,10.998 45.449,11.214 53.929,11.214
  other v1: 54.508,8.636 53.238,10.541 55.778,10.541 54.508,12.446 53.238,14.351 55.778,14.351
K2IN: IC3.1 IC3.2 J14.2 R22.2 | length 32.2
  Bottom Layer w5: 28.956,35.789 28.956,30.734 26.467,28.245 26.467,15.011 32.138,9.34 J14.2
  other v1: 25.121,23.241 25.07,25.756
K2INAMP: IC3.3 IC3.4 K2.1 | length 38.5
  Bottom Layer w5: K2.1@9.931,4.166 9.931,20.193 22.53,32.791 22.53,37.465
K2OUT: J15.1 K2.3 | length 17.1
  Top Layer w5: K2.3 21.615,11.615 25.139,11.615 27.298,9.456 J15.1
MISO: J1.6 J2.6 | length 30.9
  Top Layer w0.3: J2.6 38.676,83.55 40.454,81.772 40.454,79.998 48.702,71.75 J1.6
MOSI: J1.5 J2.5 | length 34.4
  Top Layer w0.3: J2.5 35.164,84.845 38.245,84.845 40.904,82.185 40.904,80.255 48.91,72.25 J1.5
NetC3_2: C3.2 IC1.6 | length 1.7
  Top Layer w0.6: IC1.6 35.255,24.059 C3.2@35.255,25.618
NetD1_1: D1.1 J5.2 | length 25.2
  Top Layer w1.5: J5.2 26.754,28.669 27.711,27.711 D1.1
NetD5_3: D5.3 R3.3 R10.1 R12.2 | length 11.8
  Top Layer w0.3: R3.3 16.259,62.713 21.311,62.713 21.819,62.204 R10.1 ; R12.2 R10.1 ; D5.3 25.003,62.671 24.536,62.204 R10.1
NetD8_4: D8.4 R8.1 | length 25
  Top Layer w0.3: D8.4 45.592,20.217 v1(45.593,20.218) ; v1(54.178,20.218) 63.195,29.235 R8.1
  Bottom Layer w0.3: v1(45.593,20.218) v1(54.178,20.218)
NetD9_4: D9.4 R18.1 | length 51.5
  Top Layer w0.3: R18.1 15.739,42.452 24.282,33.909 v1(33.172,33.909) ; D9.4 26.102,17.755 26.543,17.755 29.718,14.58 v1(32.537,14.58)
  Bottom Layer w0.3: v1(32.537,14.58) 31.928,15.189 31.928,27.737 33.198,29.007 33.198,33.884 v1(33.172,33.909)
NetIC2_6: IC2.6 R1.2 | length 9.9
  Top Layer w0.3: v1(48.632,50.089) 48.632,51.02 50.276,52.663 R1.2
  Bottom Layer w0.3: IC2.6 47.921,46.694 48.048,46.821 48.403,46.821 48.632,47.05 v1(48.632,50.089)
NetIC3_6: IC3.6 R2.2 | length 13.6
  Top Layer w0.3: v1(19.745,45.958) 20.634,45.069 R2.2
  Bottom Layer w0.3: v1(19.745,45.958) 22.047,48.26 25.578,48.26 26.153,47.685 26.153,45.89 25.782,45.519 25.74,45.519 25.518,45.297 IC3.6
NetK1_2: K1.2 Q1.1 R8.2 | length 33.7
  Top Layer w0.3: Q1.1@63.103,33.689 63.103,32.688 Q1.1@65.428,32.688 ; v1(63.983,21.209) 65.195,22.421 R8.2 65.195,31.743 65.428,31.976 Q1.1@65.428,32.688 ; Q1.1@65.428,33.689 Q1.1@65.428,32.688
  Bottom Layer w0.3: v1(63.983,21.209) 63.398,20.625 63.398,13.233 65.442,11.19 K1.2
NetK1_5: K1.5 Q2.3 | length 53.4
  Top Layer w0.3: K1.5 60.782,5.029 v1(63.805,8.052) ; Q2.3 56.549,45.678 56.121,45.25 56.121,42.875 58.572,40.424 58.572,38.379 60.325,36.627 v1(60.325,33.477)
  Bottom Layer w0.3: v1(60.325,33.477) 60.325,30.15 62.948,27.526 62.948,13.047 63.805,12.191 v1(63.805,8.052)
NetK2_2: K2.2 Q3.1 R18.2 | length 58.3
  Top Layer w0.3: v1(4.013,10.084) 10.946,10.084 K2.2 ; v1(10.287,42.469) 10.303,42.452 R18.2 11.617,42.468 Q3.1@11.617,44.738 ; Q3.1@11.617,45.739 11.633,45.723 11.633,44.738 13.942,44.738 Q3.1@13.942,45.739
  Bottom Layer w0.3: v1(4.013,10.084) 2.331,11.766 2.331,33.954 9.639,41.262 9.639,41.821 v1(10.287,42.469)
NetK2_5: K2.5 Q4.3 | length 38.8
  Top Layer w0.3: Q4.3 14.199,37.389 v1(15.723,37.389)
  Bottom Layer w0.3: K2.5 6.248,7.416 6.248,24.054 15.723,33.528 v1(15.723,37.389)
NetQ2_1: Q2.1 R15.1 | length 1.8
  Top Layer w0.3: R15.1 53.622,46.628 Q2.1
NetQ4_1: Q4.1 R19.1 | length 2
  Top Layer w0.3: R19.1 11.66,39.285 11.964,38.981 Q4.1
NetR3_1: R3.1 R13.3 | length 9.8
  Top Layer w0.3: R13.3 11.535,65.325 11.988,64.872 R3.1
PWM: J1.27 J2.27 | length 29.8
  Top Layer w0.3: J2.27 35.189,56.93 36.737,56.93 41.057,61.25 J1.27
RES: J1.3 J2.3 S1.1 | length 83.8
  Top Layer w0.3: S1.1@10.453,58.587 18.453,58.587 18.466,58.6 v1(18.466,60.147) ; v1(20.955,83.896) 27.508,83.896 28.804,85.192 32.97,85.192 J2.3 35.088,87.309 38.211,87.309 41.804,83.715 41.804,80.676 49.23,73.25 J1.3
  Bottom Layer w0.3: v1(18.466,60.147) 18.466,81.407 v1(20.955,83.896)
RES28: J1.28 J2.28 | length 27.1
  Top Layer w0.3: J2.28 41.548,60.75 J1.28
RES29: J1.29 J2.29 | length 30.5
  Top Layer w0.3: J2.29 35.164,54.365 36.649,54.365 42.533,60.25 J1.29
RES30: J1.30 J2.30 | length 27.7
  Top Layer w0.3: J2.30 36.458,53.07 43.138,59.75 J1.30
RES31: J1.31 J2.31 | length 31.4
  Top Layer w0.3: J2.31 35.113,51.774 36.598,51.774 37.458,52.635 37.458,53.045 43.663,59.25 J1.31
RES32: J1.32 J2.32 | length 28.9
  Top Layer w0.3: J2.32 37.908,52.03 37.908,52.859 43.799,58.75 J1.32
RXD: J1.8 J2.8 | length 29.2
  Top Layer w0.3: J2.8 38.028,81.01 48.288,70.75 J1.8
SBUF/TESTMODE: J1.13 J2.13 | length 30.5
  Top Layer w0.3: J2.13 33.927,73.39 34.977,74.44 41.042,74.44 47.232,68.25 J1.13
SCL: J1.12 J2.12 | length 27.9
  Top Layer w0.3: J2.12 40.259,75.93 47.439,68.75 J1.12
SDA: J1.11 J2.11 | length 31.2
  Top Layer w0.3: J2.11 33.927,75.93 35.095,77.098 39.798,77.098 47.647,69.25 J1.11
SWITCH: C3.1 IC1.5 L1.1 | length 7.8
  Top Layer w0.8: IC1.5 37.045,23.038 37.045,26.989 36.779,27.254 35.419,27.254 C3.1@35.255,27.418
TXD: J1.9 J2.9 | length 31.8
  Top Layer w0.3: J2.9 34.079,78.47 35.197,79.587 38.744,79.587 48.081,70.25 J1.9
VDD: C4.2 C5.2 C8.1 C9.1 C12.2 D2.2 D3.2 D4.2 D5.2 D6.2 D7.2 IC1.1 IC2.8 IC3.8 J1.2 J1.39 J2.2 J2.39 J7.1 L1.2 Q1.4 Q3.4 R1.3 R2.3 R9.1 R13.2 R16.2 | length 328.6
  Top Layer w0.3: Q3.4 11.617,47.202 11.836,47.421 R16.2 ; D4.2 30.733,79.521 v1(30.743,79.511) ; D3.2 30.741,82.84 v1(30.743,82.838) ; D2.2 30.711,86.159 v1(30.743,86.191) ; D7.2 30.963,89.478 v1(30.963,89.459) 31.954,90.45 34.588,90.45 J2.2 ; v1(59.267,55.279) 59.297,55.25 J1.39 64.021,55.25 v1(64.449,54.822) ; J1.2@61.868,73.75 63.462,73.75 63.467,73.745 v1(63.492,73.745)
  Top Layer w0.5: J7.1 1.422,50.088 1.422,39.091 3.251,37.262 9.068,37.262 9.881,38.075 v1(9.881,38.303) ; v1(10.185,46.761) 11.596,46.761 Q3.4 ; v1(16.789,49.301) 16.764,49.276 16.764,45.161 v1(18.923,43.002) 18.989,43.069 R2.3 ; R2.3@21.411,43.205 R2.3 ; R13.2 21.597,74.524 24.867,74.524 26.086,75.743 30.353,75.743 31.852,77.241 31.852,78.402 v1(30.743,79.511) ; R2.3@21.589,43.028 R2.3 ; D6.2 27.153,56.896 27.339,57.083 v1(28.736,57.083) ; D5.2 28.447,64.307 v1(28.482,64.271) ; v1(29.185,46.685) 25.273,46.685 23.266,44.679 23.266,43.409 22.926,43.069 R2.3 ; IC1.1 32.842,24.146 v1(32.842,26.111) ; v1(61.697,36.322) 61.706,36.331 R9.1 63.103,36.239 Q1.4
  Top Layer w0.8: v1(51.604,48.142) 51.604,49.115 51.927,49.437 R1.3 53.61,50.663 58.226,55.279 v1(59.267,55.279)
  Top Layer w1.5: J2.2 36.455,88.583 v1(39.963,88.583) 42.529,88.583
  Bottom Layer w0.3: v1(30.743,79.511) 31.784,80.552 31.784,82.889 ; v1(30.743,82.838) 31.734,82.838 31.784,82.889 ; v1(30.743,86.191) 31.784,86.191 ; v1(30.963,89.459) 31.784,88.637 31.784,86.191 ; v1(63.492,73.745) v1@63.518,73.771 ; 31.784,82.889 31.784,86.191
  Bottom Layer w0.5: v1(9.881,38.303) 14.224,38.303 v1(18.923,43.002) ; v1(10.185,46.761) 12.725,49.301 v1(16.789,49.301) ; C8.1@27.688,46.567 27.688,45.794 28.058,45.424 IC3.8 ; 30.217,46.669 30.226,46.669 ; v1(32.842,26.111) 38.684,26.111 ; C9.1 C9.1@50.091,48.167 ; C9.1@50.091,48.294 C9.1@50.091,48.167 ; IC2.8 50.461,46.745 50.091,47.115 C9.1@50.091,48.167 ; v1(51.604,48.142) 51.578,48.167 C9.1@50.091,48.167 ; v1(61.697,36.322) 64.338,36.322 67.35,39.334 67.35,48.804 63.729,52.426
  Bottom Layer w0.8: C8.1 30.217,46.669
  Bottom Layer w1: v1(28.482,64.271) 28.736,64.017 v1(28.736,57.083) 28.736,53.509 29.473,52.772 29.543,52.772 30.217,52.098 30.217,46.678 ; 30.226,46.669 30.217,46.678 ; 33.868,38.496 34.722,37.643 ; J2.39 30.217,44.021 30.217,46.669 30.217,46.678 ; v1@64.449,54.746 v1(64.449,54.822)
  Bottom Layer w1.5: J2.39 33.868,38.496 33.868,38.242 36.182,35.928 ; v1(39.963,88.583) 41.64,88.583 v1(41.64,88.579) 50.403,88.579 63.492,75.489 v1(63.492,73.745) 63.492,70.308 65.976,67.824 65.976,55.181 65.541,54.746 v1@64.449,54.746 ; 40.509,19.193 40.509,24.286 38.684,26.111 38.684,33.426 36.182,35.928 ; v1(59.267,55.279) 59.801,54.746 v1@64.449,54.746 ; 36.182,35.928 39.04,38.786 39.04,42.52 40.945,44.425 40.945,50.685 42.369,52.109 54.241,52.109 54.452,51.898 62.998,51.898 64.449,53.349 v1@64.449,54.746
  other v1: 41.097,16.18 41.961,17.348 41.935,18.821
pads on no net: BOH1.1 BOH2.1 D8.1 D8.2 D9.1 D9.2 J1.0 K1.4 K2.4

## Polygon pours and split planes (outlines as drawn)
K1OUT on Bottom Layer "K1out" (solid, pour order 31): 51.994,15.342 51.994,7.036 52.883,7.036 56.82,7.036 56.82,9.296 56.82,15.342 51.994,15.342
K1INAMP on Bottom Layer "K1InAmp" (solid, pour order 34): 48.616,42.215 48.616,36.5 41.961,36.5 41.529,36.5 41.529,38.125 41.529,42.215 48.641,42.215
K1IN on Bottom Layer "K1In" (solid, pour order 33): 48.692,42.189 48.692,36.551 52.577,36.551 53.899,36.551 53.899,38.1 53.899,42.164 48.718,42.164
K2INAMP on Bottom Layer "K2inAmp" (solid, pour order 37): 26.264,40.589 26.264,35.103 19.075,35.103 19.075,35.982 19.075,40.589 26.264,40.589
K2IN on Bottom Layer "K2in" (solid, pour order 36): 26.264,40.665 31.623,40.665 31.623,39.776 31.623,35.103 27.764,35.103 26.264,35.103 26.264,40.742
GND on Bottom Layer "GND_Bot" (solid, pour order 47): 0,0 0,91 68,91 68,0
VDD on Bottom Layer "VDD_bot" (solid, pour order 29): 38.608,15.215 38.608,22.073 41.478,22.073 43.078,22.073 43.078,15.215 43.078,15.164 38.684,15.164
K1INAMP on Bottom Layer "K1InAmp" (solid, pour order 43): 56.432,4.648 56.432,0 62.451,0 62.451,4.648
K2INAMP on Bottom Layer "K2InAmp" (solid, pour order 38): 6.922,5.664 6.922,0 12.941,0 12.941,5.664
K1IN on Top Layer "K1In" (solid, pour order 32): 48.692,42.189 48.692,35.509 57.582,35.509 57.582,39.802 54.229,39.802 54.229,42.189 48.737,42.159
K1OUT on Top Layer "K1out" (solid, pour order 30): 51.994,15.342 51.994,7.036 52.883,7.036 56.82,7.036 56.82,9.296 56.82,15.342 51.994,15.342
K2IN on Top Layer "K2In" (solid, pour order 35): 21.133,22.225 26.213,22.225 26.213,26.543 21.133,26.543
VDD on Top Layer "DC_DC_VDD" (solid, pour order 28): 38.405,21.692 38.405,15.443 42.596,15.443 42.596,26.912 42.596,27.737 40.095,27.737 40.095,26.615 40.095,26.659 41.351,26.659 41.351,22.696 41.351,21.692 38.405,21.692
12V on Top Layer "DC_DC_12V" (solid, pour order 27): 31.217,23.546 33.63,23.546 33.63,21.057 34.341,21.057 34.341,19.126 33.909,19.126 33.909,15.443 30.175,15.443 30.175,20.396 30.175,20.32 31.445,20.32 31.217,20.32 31.217,23.546
GND on Top Layer "DC_DC_GND" (solid, pour order 26): 32.868,25.121 32.868,23.495 33.579,23.495 33.579,22.098 33.35,22.098 33.35,21.057 34.341,21.057 34.341,19.126 33.909,19.126 33.909,15.443 38.405,15.443 38.405,22.428 34.214,22.428 34.214,25.121
GND on Top Layer "GND_Top" (solid, pour order 45): 0,0 0,91 68,91 68,0
K1OUT on Top Layer "K1out" (solid, pour order 41): 67.716,20.015 63.704,20.015 63.704,16.352 63.704,14.021 67.005,14.021 67.716,14.021 67.716,20.015

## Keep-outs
Keep-Out Layer:
  the board outline again, w0.5

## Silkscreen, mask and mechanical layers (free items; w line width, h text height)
Top Overlay:
  lines w0.1: 13.335,30.641 13.335,31.123 ; 13.335,31.318 13.335,31.801 ; 13.335,31.996 13.335,32.478 ; 13.335,32.673 13.335,33.155 ; 13.716,30.59 13.716,33.155
  text "IN4" at 0.517,89.595 h1 r270
  text "IN4" at 9.492,89.469 h1 r270
  text "GND" at 30.438,88.426 h0.8
  text "VDD" at 38.422,87.868 h1
  text "IN5" at 0.517,86.826 h1 r270
  text "IN5" at 9.492,86.7 h1 r270
  text "CS" at 38.422,85.328 h1
  text "RES" at 30.606,85.023 h0.8
  text "MOSI" at 30.184,83.118 h0.8
  text "IN6" at 0.517,83.042 h1 r270
  text "IN6" at 9.492,82.916 h1 r270
  text "MISO" at 38.422,82.788 h1
  text "CLK" at 30.606,80.73 h0.8
  text "IN7" at 0.517,80.578 h1 r270
  text "IN7" at 9.492,80.452 h1 r270
  text "RXD" at 38.422,80.248 h1
  text "TXD" at 30.606,78.19 h0.8
  text "DE" at 38.422,77.708 h1
  text "SDA" at 29.278,75.168 h1
  text "SCL" at 38.422,75.168 h1
  text "A/D0" at 0.631,74.634 h0.8 r270
  text "SBUF" at 28.483,72.628 h1
  text "DPROT" at 38.422,72.628 h1
  text "GND" at 0.686,71.45 h0.8 r270
  text "A/D 0" at 27.754,70.088 h1
  text "A/D 1" at 38.422,70.088 h1
  text "A/D1" at 0.631,68.259 h0.8 r270
  text "A/D 2" at 27.754,67.548 h1
  text "A/D 3" at 38.422,67.548 h1
  text "GND" at 0.61,65.278 h0.8 r270
  text "I/O 0" at 28.516,65.008 h1
  text "I/O 1" at 38.422,65.008 h1
  text "Screw" at 15.046,64.779 h1
  text "A/D0" at 20.999,64.398 h1 r270
  text "Poti" at 10.677,63.433 h1
  text "Header" at 14.859,63.398 h1
  text "I/O 2" at 28.516,62.468 h1
  text "I/O 3" at 38.422,62.468 h1
  text "GND" at 20.999,60.639 h1 r270
  text "I/O 4" at 28.516,59.928 h1
  text "I/O 5" at 38.422,59.928 h1
  text "GND" at 8.179,58.877 h0.8 r270
  text "A/D1" at 20.999,57.642 h1 r270
  text "I/O 6" at 28.567,57.388 h1
  text "I/O 7" at 38.422,57.388 h1
  text "GND" at 20.999,54.187 h1 r270
  text "3.3V" at 2.13,53.712 h0.8 r270
  text "Vin" at 7.864,53.483 h0.8 r270
  text "A/D0" at 7.921,51.477 h0.8 r270
  text "Reset" at 13.065,51.342 h1
  text "A/D1" at 2.13,51.274 h0.8 r270
  text "IN4" at 7.921,48.429 h0.8 r270
  text "IN5" at 2.13,48.302 h0.8 r270
  text "BUZZER" at 38.422,47.482 h0.8
  text "12 V" at 28.902,47.456 h1
  text "IN7" at 2.13,45.889 h0.8 r270
  text "IN6" at 7.921,45.863 h0.8 r270
  text "I/O CLK" at 38.422,44.971 h0.8
  text "I/O SDA" at 26.807,44.882 h1
  text "IRLY0" at 1.342,44.009 h0.8 r270
  text "RLY0" at 8.505,43.882 h0.8 r270
  text "A/D2" at 2.447,43.628 h0.6 r270
  text "Out0" at 7.705,43.527 h0.6 r270
  text "I/O INT" at 27.531,42.342 h1
  text "I/O RTC" at 38.422,42.347 h0.8
  text "RLY1" at 8.505,41.037 h0.8 r270
  text "IRLY1" at 1.342,40.936 h0.8 r270
  text "A/D3" at 2.447,40.86 h0.6 r270
  text "Out1" at 7.705,40.682 h0.6 r270
  text "VDD" at 29.625,39.658 h1
  text "GND" at 38.422,39.608 h1
  text "-" at 10.888,33.74 h1 r90
  text "5-30V" at 12.09,33.613 h0.8 r270
  text "RLY0" at 42.605,28.457 h1
  text "+" at 10.944,27.748 h1 r90
  text "+12V" at 42.605,27.035 h1
  text "RLY1" at 20.837,25.688 h1
  text "+12V" at 20.837,24.266 h1
  text "GND" at 21.201,11.82 h1
  text "RLY1" at 28.178,11.82 h1
  text "+" at 32.191,11.82 h1
  text "GND" at 36.28,11.82 h1
  text "RLY0" at 43.519,11.82 h1
  text "+" at 47.532,11.82 h1
  text "-" at 25.968,11.773 h1
  text "-" at 41.309,11.773 h1
  text "GND" at 21.303,0.593 h1
  text "RLY1" at 28.279,0.593 h1
  text "+" at 32.292,0.593 h1
  text "GND" at 36.382,0.593 h1
  text "RLY0" at 43.621,0.593 h1
  text "+" at 47.634,0.593 h1
  text "-" at 26.069,0.546 h1
  text "-" at 41.411,0.546 h1
Bottom Overlay:
  drawing of 4215 lines, arcs and shapes, not listed
  text "Rev C" at 27.831,85.734 h1 r270
  text "EA 94998-C" at 29.888,80.781 h1 r270
Mechanical 15:
  lines w0.1: 63.855,27.408 10.457,27.416 10.457,104.076 68.857,104.076 68.857,27.407 ; 23.868,37.5 68.868,37.5 68.868,91.5 23.868,91.5 23.868,37.5

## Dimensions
0,0 to 68,0 on Mechanical 1
0,91 to 0,0 on Mechanical 1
